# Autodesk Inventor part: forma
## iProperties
Created: 2008-07
Part Number: forma
Document SubType Name: Modeling
Designer: Inteus
Density: 1 g/cm^3
Author: Inteus
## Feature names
1. Extrusion1
2. Extrusion4
3. Extrusion5
4. Fillet1
5. Fillet2
6. Extrusion6
7. Extrusion8
8. Rectangular Pattern1
9. Extrusion9
10. Extrusion10
11. Fillet3
12. Extrusion11
